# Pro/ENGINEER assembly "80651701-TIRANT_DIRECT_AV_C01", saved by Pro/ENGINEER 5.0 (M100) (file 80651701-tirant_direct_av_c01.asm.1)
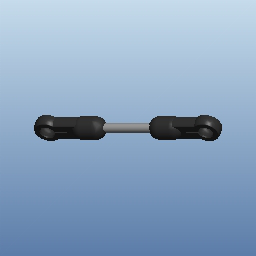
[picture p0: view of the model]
Units: millimeter Newton Second (mmNs); MM, TONNE, HOURS

Other components: 80022001-CHAPE_STD-DR_C01, 80465046-TIRANT_ACIER_LONG2_C01, 80022001-CHAPE_STD-DR_C01

Other named items: A-DROITE, A-DESSUS, A-FACE, A-R0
